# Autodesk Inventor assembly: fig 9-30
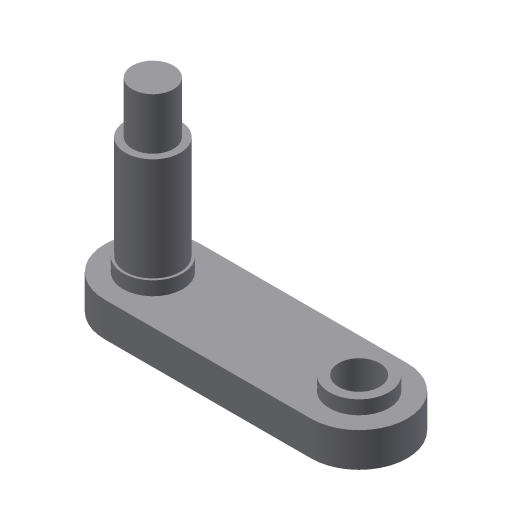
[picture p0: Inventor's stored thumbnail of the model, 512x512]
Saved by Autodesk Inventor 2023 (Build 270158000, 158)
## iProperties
Created: 2002-01
Part Number: fig 9-30
Document SubType Name: Assembly
Designer: ***
Control State: 0
Master: False
Checked Out: False
Shininess: 64.0
Length Units: 11269
Angle Units: 11279
Time Units: 11290
Mass Units: 11283
Length Display Precision: 3
Angle Display Precision: 2
Density: 0.0
Volumn: 0.0
Area: 0.0
PropertySet Name: Model Information
Author: ***
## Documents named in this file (3)
- D:\PROJECTS\Project 2022\Autodesk Inventor For Professional 2023\RESOURCES INVENTOR 2023\RESOURCES INVENTOR 2023\Inventor_2023_Part\Inventor_2023_Part\c09_Inv_2023_prt\fig 9-34.iam
- D:\PROJECTS\Project 2022\Autodesk Inventor For Professional 2023\RESOURCES INVENTOR 2023\RESOURCES INVENTOR 2023\Inventor_2023_Part\Inventor_2023_Part\c09_Inv_2023_prt\Part5.ipt
- D:\PROJECTS\Project 2022\Autodesk Inventor For Professional 2023\RESOURCES INVENTOR 2023\RESOURCES INVENTOR 2023\Inventor_2023_Part\Inventor_2023_Part\c09_Inv_2023_prt\Part6.ipt
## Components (2 placed, 2 different names)
1. Part5:1 — Insert:1
2. Part6:1 — Insert:1
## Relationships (1: Insert 1)
- Insert:1: Part5:1 ↔ Part6:1
